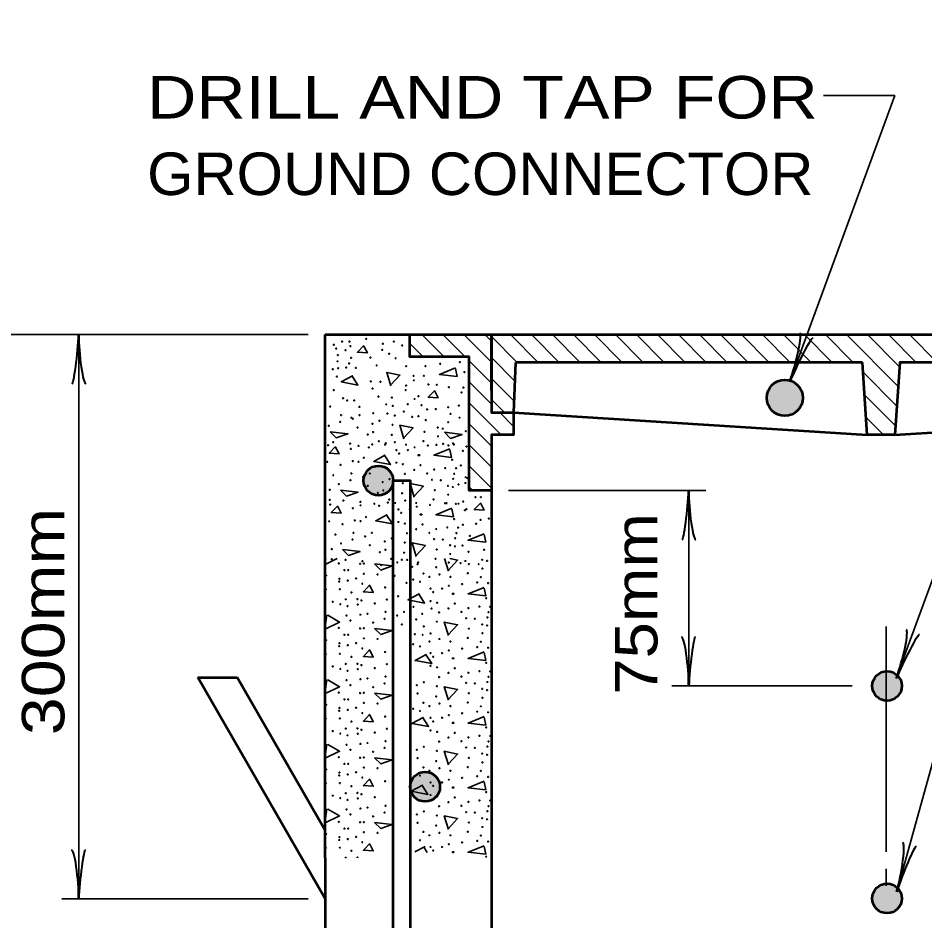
# Model space of a CAD drawing. Extents: x 918 to 1774, y -8 to 536.
# Drawn here: x 1039.5 to 1103.6, y 193.7 to 257.4 of the extents above; entities that cross this region are included whole.
import ezdxf

# ---------------------------------------------------------------- set-up
doc = ezdxf.new("R2010")
doc.units = 0
doc.header["$LTSCALE"] = 1.2
doc.layers.add('1', color=7, linetype='Continuous', lineweight=35)

msp = doc.modelspace()

# ---------------------------------------------------------------- hatches: boundary and pattern name
at = {"layer": '1'}
for points in [[(1094.941, 230.59, 1), (1092.39, 230.59, 1)], [(1066.027, 224.745, 1), (1063.934, 224.745, 1)], [(1101.93, 210.254, 1), (1099.837, 210.254, 1)], [(1069.326, 203.145, 1), (1067.222, 203.145, 1)], [(1101.93, 195.259, 1), (1099.837, 195.259, 1)]]:
    msp.add_hatch(color=256, dxfattribs=at).paths.add_polyline_path(points)

# ---------------------------------------------------------------- linework, layer by layer
for p, q in [((1060.028, 235.047), (1028.227, 235.047)), ((1043.828, 235.047), (1043.828, 195.243)), ((1069.615, 233.475), (1068.043, 235.047)), ((1071.097, 233.475), (1069.525, 235.047)), ((1072.952, 233.102), (1071.007, 235.047)), ((1072.952, 234.584), (1072.489, 235.047)), ((1072.952, 234.914), (1074.784, 233.082)), ((1074.301, 235.047), (1076.266, 233.082)), ((1075.783, 235.047), (1077.748, 233.082)), ((1077.265, 235.047), (1079.23, 233.082)), ((1078.747, 235.047), (1080.712, 233.082)), ((1080.229, 235.047), (1082.194, 233.082)), ((1081.711, 235.047), (1083.676, 233.082)), ((1083.193, 235.047), (1085.158, 233.082)), ((1084.675, 235.047), (1086.639, 233.082)), ((1086.157, 235.047), (1088.122, 233.082)), ((1087.639, 235.047), (1089.604, 233.082)), ((1089.121, 235.047), (1091.086, 233.082)), ((1090.603, 235.047), (1092.568, 233.082)), ((1092.085, 235.047), (1094.049, 233.082)), ((1093.567, 235.047), (1095.532, 233.082)), ((1095.049, 235.047), (1097.014, 233.082)), ((1096.531, 235.047), (1098.495, 233.082)), ((1098.013, 235.047), (1101.662, 231.397)), ((1099.495, 235.047), (1101.758, 232.783)), ((1100.977, 235.047), (1102.942, 233.082)), ((1102.459, 235.047), (1104.424, 233.082)), ((1068.133, 233.475), (1067.188, 234.42)), ((1072.952, 231.621), (1071.38, 233.192)), ((1072.952, 233.432), (1074.609, 231.775)), ((1099.188, 232.389), (1101.567, 230.011)), ((1072.952, 231.95), (1074.554, 230.347)), ((1072.952, 230.138), (1071.38, 231.71)), ((1072.952, 230.468), (1073.874, 229.545)), ((1099.298, 230.797), (1101.471, 228.624)), ((1073.635, 227.973), (1071.38, 230.228)), ((1074.523, 228.567), (1073.545, 229.545)), ((1099.408, 229.205), (1100.64, 227.973)), ((1072.952, 227.175), (1071.38, 228.746)), ((1072.952, 225.692), (1071.38, 227.264)), ((1072.952, 224.211), (1071.38, 225.782)), ((1071.08, 225.019), (1071.38, 224.847)), ((1071.637, 224.043), (1071.38, 224.3)), ((1074.151, 224.043), (1088.09, 224.043)), ((1086.889, 210.254), (1086.889, 224.043)), ((1062.07, 219.243), (1061.227, 218.832)), ((1061.227, 218.98), (1061.265, 219.243)), ((1069.917, 218.365), (1069.653, 219.243)), ((1061.227, 214.42), (1061.349, 215.269)), ((1100.828, 214.443), (1100.828, 198.543)), ((1061.227, 209.86), (1061.349, 210.709)), ((1098.428, 210.254), (1085.689, 210.254)), ((1061.227, 205.3), (1061.349, 206.149)), ((1061.227, 200.74), (1061.349, 201.589)), ((1068.27, 198.934), (1067.547, 198.54)), ((1068.425, 198.496), (1068.156, 198.914)), ((1100.828, 197.343), (1100.828, 196.143)), ((1060.028, 195.243), (1042.628, 195.243))]:
    msp.add_line(p, q, dxfattribs=at)
at = {"layer": '1', "lineweight": 53}
for p, q in [((1061.227, 198.122), (1061.227, 235.047)), ((1072.952, 235.047), (1127.967, 235.047)), ((1072.952, 231.117), (1072.952, 235.047)), ((1074.659, 233.082), (1074.523, 229.545)), ((1099.141, 233.082), (1074.659, 233.082)), ((1074.523, 229.545), (1099.493, 227.973)), ((1101.426, 227.973), (1126.396, 229.545)), ((1072.952, 224.043), (1072.952, 198.122)), ((1061.227, 195.243), (1052.227, 210.843)), ((1052.227, 210.843), (1054.998, 210.843)), ((1061.227, 200.046), (1054.998, 210.843)), ((1061.227, 198.122), (1061.227, 163.476)), ((1072.952, 198.122), (1072.952, 158.043))]:
    msp.add_line(p, q, dxfattribs=at)
at = {"layer": '1'}
for points in [[(1101.54, 210.795), (1118.692, 257.384), (1101.575, 195.743)], [(1094.021, 231.736), (1101.428, 251.913), (1096.398, 251.913)], [(1063.958, 234.285), (1063.502, 233.805), (1064.198, 233.757), (1063.958, 234.237)], [(1065.855, 231.427), (1065.567, 232.387), (1066.503, 232.195), (1065.831, 231.475)], [(1070.412, 232.702), (1069.284, 232.246), (1070.532, 232.102), (1070.412, 232.654)], [(1063.148, 232.141), (1062.356, 231.709), (1063.532, 231.493), (1063.1, 232.165)], [(1068.957, 231.114), (1068.501, 230.634), (1069.197, 230.586), (1068.957, 231.066)], [(1066.782, 227.695), (1066.494, 228.655), (1067.43, 228.463), (1066.758, 227.743)], [(1061.96, 227.155), (1061.504, 226.675), (1062.2, 226.627), (1061.96, 227.107)], [(1070.024, 226.987), (1068.896, 226.531), (1070.144, 226.387), (1070.024, 226.939)], [(1065.44, 226.531), (1064.648, 226.099), (1065.824, 225.883), (1065.392, 226.555)], [(1067.504, 223.579), (1067.216, 224.538), (1068.152, 224.347), (1067.48, 223.627)], [(1062.104, 222.966), (1061.648, 222.486), (1062.344, 222.438), (1062.104, 222.918)], [(1070.168, 222.798), (1069.04, 222.342), (1070.288, 222.198), (1070.168, 222.75)], [(1072.201, 223.186), (1071.745, 222.706), (1072.441, 222.658), (1072.201, 223.138)], [(1065.584, 222.342), (1064.792, 221.91), (1065.968, 221.694), (1065.536, 222.366)], [(1072.436, 220.993), (1071.308, 220.537), (1072.556, 220.393), (1072.436, 220.945)], [(1067.648, 219.39), (1067.36, 220.35), (1068.296, 220.158), (1067.624, 219.438)], [(1070.025, 219.243), (1070.565, 219.133), (1069.893, 218.413)], [(1064.373, 217.381), (1063.917, 216.901), (1064.613, 216.853), (1064.373, 217.333)], [(1072.437, 217.213), (1071.309, 216.757), (1072.557, 216.613), (1072.437, 217.165)], [(1067.853, 216.757), (1067.061, 216.325), (1068.237, 216.109), (1067.805, 216.781)], [(1061.397, 215.245), (1062.237, 214.765), (1061.227, 214.272)], [(1069.917, 213.805), (1069.629, 214.765), (1070.565, 214.573), (1069.893, 213.853)], [(1064.373, 212.821), (1063.917, 212.341), (1064.613, 212.293), (1064.373, 212.773)], [(1072.437, 212.653), (1071.309, 212.197), (1072.557, 212.053), (1072.437, 212.605)], [(1068.358, 212.482), (1067.566, 212.05), (1068.742, 211.834), (1068.31, 212.506)], [(1061.397, 210.685), (1062.237, 210.205), (1061.227, 209.712)], [(1069.917, 209.245), (1069.629, 210.205), (1070.565, 210.013), (1069.893, 209.293)], [(1064.373, 208.261), (1063.917, 207.781), (1064.613, 207.733), (1064.373, 208.213)], [(1068.138, 208.032), (1067.346, 207.6), (1068.522, 207.384), (1068.09, 208.056)], [(1072.437, 208.093), (1071.309, 207.637), (1072.557, 207.493), (1072.437, 208.045)], [(1061.397, 206.125), (1062.237, 205.645), (1061.227, 205.152)], [(1069.917, 204.685), (1069.629, 205.645), (1070.565, 205.453), (1069.893, 204.733)], [(1064.373, 203.701), (1063.917, 203.221), (1064.613, 203.173), (1064.373, 203.653)], [(1068.094, 203.252), (1067.302, 202.82), (1068.478, 202.604), (1068.046, 203.276)], [(1072.437, 203.533), (1071.309, 203.077), (1072.557, 202.933), (1072.437, 203.485)], [(1061.397, 201.565), (1062.237, 201.085), (1061.227, 200.592)], [(1069.917, 200.125), (1069.629, 201.085), (1070.565, 200.893), (1069.893, 200.173)], [(1064.373, 199.141), (1063.917, 198.661), (1064.613, 198.613), (1064.373, 199.093)], [(1072.437, 198.973), (1071.309, 198.517), (1072.557, 198.373), (1072.437, 198.925)]]:
    msp.add_lwpolyline(points, dxfattribs=at)
at = {"layer": '1', "lineweight": 53}
for points in [[(1061.227, 235.047), (1072.952, 235.047), (1072.952, 229.545), (1074.523, 229.545), (1074.523, 227.973), (1072.952, 227.973), (1072.952, 224.043), (1071.38, 224.043), (1071.38, 233.475), (1067.188, 233.475), (1067.188, 235.047)], [(1126.26, 233.082), (1101.778, 233.082), (1101.426, 227.973), (1099.493, 227.973), (1099.141, 233.082)]]:
    msp.add_lwpolyline(points, dxfattribs=at)
at = {"layer": '1'}
for points in [[(1061.574, 228.199), (1062.822, 228.055), (1062.006, 227.767)], [(1069.636, 228.156), (1070.884, 228.012), (1070.068, 227.724)], [(1062.296, 224.083), (1063.544, 223.939), (1062.728, 223.651)], [(1062.44, 219.894), (1063.688, 219.75), (1062.872, 219.462)], [(1064.709, 218.869), (1065.957, 218.725), (1065.141, 218.437)], [(1064.709, 214.309), (1065.957, 214.165), (1065.141, 213.877)], [(1064.709, 209.749), (1065.957, 209.605), (1065.141, 209.317)], [(1064.709, 205.189), (1065.957, 205.045), (1065.141, 204.757)], [(1064.709, 200.629), (1065.957, 200.485), (1065.141, 200.197)]]:
    msp.add_lwpolyline(points, close=True, dxfattribs=at)
at = {"layer": '1', "lineweight": 53}
msp.add_lwpolyline([(1066.028, 152.043), (1066.028, 224.745), (1067.227, 224.745), (1067.227, 153.243), (1091.227, 153.243), (1091.227, 152.043)], close=True, dxfattribs=at)
at = {"layer": '1'}
for centre in [(1061.831, 234.336), (1062.417, 234.555), (1062.929, 234.555), (1064.124, 234.751), (1065.294, 234.409), (1066.075, 234.555), (1066.66, 234.287), (1062.002, 234.068), (1062.124, 233.604), (1062.661, 233.946), (1063.002, 234.238), (1065.246, 233.97), (1065.733, 233.702), (1062.1, 233.165), (1062.904, 233.019), (1063.051, 233.409), (1064.416, 233.433), (1066.197, 233.385), (1069.343, 232.994), (1070.733, 233.116), (1061.758, 232.604), (1062.148, 232.677), (1062.709, 232.726), (1063.392, 232.701), (1064.855, 232.872), (1066.928, 232.823), (1068.294, 232.823), (1071.05, 232.409), (1062.051, 232.092), (1064.441, 231.75), (1065.124, 231.726), (1067.465, 232.14), (1067.489, 231.823), (1068.196, 232.14), (1061.831, 231.14), (1064.563, 231.238), (1066.904, 231.14), (1066.928, 231.457), (1068.513, 231.531), (1069.099, 231.506), (1069.952, 231.335), (1070.976, 231.311), (1062.49, 230.555), (1062.783, 230.408), (1063.27, 230.408), (1064.977, 230.677), (1065.928, 230.604), (1067.538, 230.506), (1067.806, 230.701), (1070.855, 230.969), (1061.583, 229.971), (1063.636, 229.945), (1065.528, 230.13), (1065.989, 230.019), (1067.05, 230.14), (1068.026, 230.067), (1068.416, 229.774), (1069.026, 229.798), (1069.903, 229.92), (1070.659, 230.042), (1062.347, 229.367), (1063.075, 229.189), (1063.651, 229.367), (1064.612, 229.506), (1065.611, 229.481), (1066.132, 229.335), (1066.784, 229.621), (1067.367, 229.237), (1067.806, 229.286), (1070.074, 229.457), (1070.708, 229.189), (1061.472, 228.619), (1062.283, 228.889), (1063.174, 229.112), (1063.508, 228.492), (1064.557, 228.762), (1065.05, 228.969), (1065.973, 228.683), (1068.318, 229.018), (1069.17, 228.492), (1069.903, 228.872), (1064.224, 227.999), (1064.605, 228.174), (1065.925, 227.967), (1068.231, 228.19), (1069.186, 227.871), (1069.519, 228.412), (1071.142, 228.237), (1061.431, 227.239), (1061.79, 227.458), (1062.983, 227.362), (1064.548, 227.303), (1065.019, 227.521), (1065.448, 227.283), (1065.502, 227.382), (1066.148, 227.458), (1066.927, 227.283), (1068.152, 227.537), (1068.476, 227.223), (1069.074, 227.267), (1069.542, 227.335), (1069.917, 227.235), (1070.251, 227.378), (1070.305, 227.287), (1063.037, 226.985), (1063.578, 227.191), (1064.303, 227.092), (1066.249, 226.905), (1066.44, 226.65), (1067.061, 226.905), (1067.538, 227.096), (1070.941, 226.841), (1071.189, 227.155), (1061.367, 226.062), (1063.164, 226.125), (1063.578, 226.078), (1063.959, 226.364), (1066.25, 226.014), (1067.808, 226.539), (1067.872, 226.539), (1070.178, 226.221), (1062.305, 225.855), (1066.711, 225.903), (1067.506, 225.505), (1067.951, 225.839), (1068.921, 225.521), (1069.701, 225.632), (1070.464, 225.616), (1070.798, 225.823), (1061.796, 225.123), (1063.005, 224.773), (1063.069, 225.25), (1063.896, 224.996), (1064.373, 225.25), (1065.279, 224.646), (1065.772, 224.853), (1066.854, 225.219), (1068.428, 225.25), (1068.762, 224.805), (1069.383, 224.773), (1070.257, 224.869), (1070.337, 225.235), (1061.542, 224.105), (1062.194, 224.503), (1064.23, 224.375), (1065.327, 224.057), (1066.695, 224.566), (1068.953, 224.073), (1069.891, 224.375), (1070.241, 224.296), (1070.632, 224.482), (1071.119, 224.579), (1061.542, 223.389), (1064.945, 223.882), (1065.741, 223.405), (1066.647, 223.85), (1068.874, 223.421), (1069.907, 223.755), (1071.827, 223.579), (1072.217, 223.579), (1061.575, 223.051), (1062.512, 223.341), (1063.181, 222.796), (1063.705, 223.246), (1063.722, 223.003), (1064.692, 223.114), (1065.025, 222.976), (1065.646, 223.194), (1066.17, 223.166), (1066.87, 223.341), (1067.649, 223.166), (1067.682, 222.907), (1068.62, 223.035), (1069.686, 223.146), (1069.796, 223.151), (1070.449, 223.098), (1070.639, 223.119), (1070.973, 223.262), (1071.192, 222.725), (1064.104, 222.176), (1066.394, 222.717), (1066.585, 222.462), (1067.205, 222.717), (1067.953, 222.351), (1068.016, 222.351), (1071.086, 222.653), (1061.512, 221.873), (1062.45, 221.666), (1063.309, 221.937), (1063.722, 221.889), (1066.394, 221.826), (1066.855, 221.714), (1068.096, 221.651), (1069.845, 221.444), (1070.322, 222.032), (1070.942, 221.635), (1071.875, 221.701), (1072.192, 221.969), (1072.778, 222.066), (1061.941, 220.935), (1063.213, 221.062), (1064.04, 220.807), (1064.517, 221.062), (1066.998, 221.03), (1067.65, 221.317), (1068.573, 221.062), (1069.066, 221.332), (1070.481, 221.046), (1070.608, 221.428), (1071.436, 220.847), (1062.338, 220.314), (1063.15, 220.585), (1064.374, 220.187), (1065.424, 220.457), (1065.917, 220.664), (1066.839, 220.378), (1068.907, 220.617), (1069.527, 220.585), (1070.036, 220.187), (1070.402, 220.68), (1070.924, 220.164), (1061.686, 219.917), (1065.09, 219.694), (1065.472, 219.869), (1066.792, 219.662), (1069.098, 219.885), (1070.052, 219.567), (1070.386, 220.107), (1071.339, 219.725), (1072.436, 219.871), (1061.686, 219.201), (1062.18, 218.907), (1062.657, 219.153), (1063.849, 219.057), (1063.955, 218.891), (1065.885, 219.217), (1066.314, 218.978), (1066.643, 219.162), (1067.014, 219.153), (1067.793, 218.978), (1069.018, 219.232), (1069.941, 218.962), (1070.783, 218.93), (1071.117, 219.073), (1072.304, 219.162), (1072.654, 219.082), (1062.578, 218.43), (1062.848, 218.43), (1063.683, 218.873), (1065.169, 218.787), (1067.358, 218.669), (1067.74, 218.844), (1069.06, 218.637), (1071.366, 218.859), (1072.056, 218.851), (1072.32, 218.541), (1061.29, 218.048), (1062.212, 217.624), (1062.228, 217.825), (1062.816, 217.688), (1063.405, 217.841), (1063.955, 218.175), (1064.925, 218.128), (1066.118, 218.032), (1067.438, 217.762), (1067.915, 217.608), (1068.153, 218.191), (1068.583, 217.953), (1069.283, 218.128), (1070.062, 217.953), (1071.286, 218.207), (1072.209, 217.937), (1062.26, 217.083), (1063.844, 217.465), (1065.45, 217.211), (1065.991, 217.417), (1066.961, 217.529), (1068.662, 217.131), (1069.473, 217.131), (1069.951, 217.322), (1070.889, 217.449), (1071.954, 217.561), (1072.718, 217.513), (1062.673, 216.368), (1063.071, 216.861), (1063.5, 216.383), (1065.577, 216.352), (1066.372, 216.59), (1068.853, 216.877), (1070.221, 216.765), (1070.285, 216.765), (1072.591, 216.447), (1061.751, 216.193), (1062.292, 216.018), (1062.801, 215.89), (1063.516, 216.002), (1063.78, 216.288), (1064.718, 216.081), (1065.991, 216.304), (1067.457, 215.837), (1068.662, 216.24), (1068.735, 215.711), (1069.124, 216.129), (1069.919, 215.731), (1070.364, 216.065), (1071.334, 215.747), (1072.113, 215.859), (1072.877, 215.843), (1062.737, 215.222), (1063.707, 215.286), (1064.209, 215.349), (1065.482, 215.477), (1066.309, 215.222), (1066.786, 215.477), (1068.077, 215.344), (1069.267, 215.445), (1070.841, 215.477), (1072.67, 215.095), (1072.75, 215.461), (1063.007, 214.872), (1064.607, 214.729), (1065.418, 214.999), (1066.643, 214.602), (1067.647, 214.951), (1068.179, 214.458), (1069.108, 214.793), (1071.175, 215.031), (1071.795, 214.999), (1072.304, 214.602), (1072.654, 214.522), (1062.18, 214.347), (1062.578, 213.87), (1062.848, 213.87), (1063.683, 214.313), (1063.955, 214.331), (1067.559, 213.901), (1068.103, 213.863), (1068.659, 213.964), (1071.366, 214.299), (1072.32, 213.981), (1061.29, 213.488), (1062.228, 213.265), (1062.816, 213.128), (1063.405, 213.281), (1063.955, 213.615), (1064.925, 213.568), (1067.438, 213.202), (1068.583, 213.393), (1069.283, 213.568), (1070.062, 213.393), (1071.286, 213.647), (1072.209, 213.377), (1062.212, 213.064), (1062.26, 212.523), (1063.844, 212.905), (1065.45, 212.651), (1067.915, 213.048), (1068.662, 212.571), (1069.473, 212.571), (1069.951, 212.762), (1070.889, 212.889), (1071.954, 213.001), (1072.718, 212.953), (1063.071, 212.301), (1068.853, 212.317), (1070.221, 212.205), (1070.285, 212.205), (1072.591, 211.887), (1061.751, 211.633), (1062.292, 211.458), (1062.673, 211.808), (1062.801, 211.33), (1063.5, 211.823), (1063.516, 211.442), (1063.78, 211.728), (1064.718, 211.521), (1065.577, 211.792), (1068.662, 211.68), (1069.124, 211.569), (1070.364, 211.505), (1072.113, 211.299), (1072.877, 211.283), (1062.737, 210.662), (1063.707, 210.726), (1064.209, 210.789), (1065.482, 210.917), (1069.267, 210.885), (1069.919, 211.171), (1070.841, 210.917), (1071.334, 211.187), (1072.75, 210.901), (1063.007, 210.312), (1064.607, 210.169), (1065.418, 210.439), (1067.692, 210.312), (1068.185, 210.519), (1069.108, 210.233), (1071.175, 210.471), (1071.795, 210.439), (1072.304, 210.042), (1072.654, 209.962), (1072.67, 210.535), (1062.18, 209.787), (1062.578, 209.31), (1062.848, 209.31), (1063.683, 209.753), (1063.955, 209.771), (1067.74, 209.724), (1069.06, 209.517), (1071.366, 209.739), (1072.32, 209.421), (1061.29, 208.928), (1062.228, 208.705), (1063.405, 208.721), (1063.955, 209.055), (1064.925, 209.008), (1067.438, 208.642), (1068.153, 209.071), (1068.583, 208.833), (1069.283, 209.008), (1070.062, 208.833), (1071.286, 209.087), (1072.209, 208.817), (1062.212, 208.504), (1062.816, 208.568), (1063.844, 208.345), (1065.45, 208.091), (1067.915, 208.488), (1068.662, 208.011), (1069.473, 208.011), (1069.951, 208.202), (1070.889, 208.329), (1071.954, 208.441), (1072.718, 208.393), (1062.26, 207.963), (1063.071, 207.741), (1068.853, 207.757), (1070.221, 207.645), (1070.285, 207.645), (1061.751, 207.073), (1062.292, 206.898), (1062.673, 207.248), (1062.801, 206.77), (1063.5, 207.263), (1063.516, 206.882), (1063.78, 207.168), (1064.718, 206.961), (1065.577, 207.232), (1068.662, 207.12), (1069.124, 207.009), (1070.364, 206.945), (1072.113, 206.739), (1072.591, 207.327), (1072.877, 206.723), (1062.737, 206.102), (1063.707, 206.166), (1064.209, 206.229), (1065.482, 206.357), (1069.267, 206.325), (1069.919, 206.611), (1070.841, 206.357), (1071.334, 206.627), (1072.75, 206.341), (1063.007, 205.752), (1064.607, 205.609), (1065.418, 205.879), (1067.692, 205.752), (1068.185, 205.959), (1069.108, 205.673), (1071.175, 205.911), (1071.795, 205.879), (1072.304, 205.482), (1072.67, 205.975), (1062.18, 205.227), (1063.683, 205.193), (1063.955, 205.211), (1067.74, 205.164), (1069.06, 204.957), (1071.366, 205.179), (1072.32, 204.861), (1072.654, 205.402), (1061.29, 204.368), (1062.578, 204.75), (1062.848, 204.75), (1063.405, 204.161), (1063.955, 204.495), (1064.925, 204.448), (1068.153, 204.511), (1068.583, 204.273), (1069.283, 204.448), (1070.062, 204.273), (1071.286, 204.527), (1072.209, 204.257), (1062.212, 203.944), (1062.228, 204.145), (1062.816, 204.008), (1063.844, 203.785), (1065.45, 203.531), (1067.915, 203.928), (1069.951, 203.642), (1070.889, 203.769), (1071.954, 203.881), (1072.718, 203.833), (1062.26, 203.403), (1063.071, 203.181), (1068.662, 203.451), (1068.853, 203.197), (1069.473, 203.451), (1070.221, 203.085), (1070.285, 203.085), (1061.751, 202.513), (1062.292, 202.338), (1062.673, 202.688), (1063.5, 202.703), (1063.516, 202.322), (1063.78, 202.608), (1064.718, 202.401), (1068.662, 202.56), (1069.124, 202.449), (1070.364, 202.385), (1072.591, 202.767), (1062.801, 202.21), (1063.707, 201.606), (1064.209, 201.669), (1065.482, 201.797), (1069.267, 201.765), (1069.919, 202.051), (1070.841, 201.797), (1071.334, 202.067), (1072.113, 202.179), (1072.75, 201.781), (1072.877, 202.163), (1062.737, 201.542), (1063.007, 201.192), (1064.607, 201.049), (1065.418, 201.319), (1067.692, 201.192), (1068.185, 201.399), (1069.108, 201.113), (1071.175, 201.351), (1071.795, 201.319), (1072.67, 201.415), (1062.18, 200.667), (1063.683, 200.633), (1063.955, 200.651), (1067.74, 200.604), (1069.06, 200.397), (1071.366, 200.619), (1072.304, 200.922), (1072.654, 200.842), (1061.29, 199.808), (1062.578, 200.19), (1062.848, 200.19), (1063.955, 199.935), (1064.925, 199.888), (1068.153, 199.951), (1068.583, 199.713), (1069.283, 199.888), (1070.062, 199.713), (1071.286, 199.967), (1072.209, 199.697), (1072.32, 200.301), (1062.212, 199.384), (1062.228, 199.585), (1062.816, 199.448), (1063.405, 199.601), (1063.844, 199.225), (1067.915, 199.368), (1069.951, 199.082), (1070.889, 199.209), (1071.954, 199.321), (1072.718, 199.273), (1062.26, 198.843), (1063.071, 198.621), (1068.662, 198.891), (1068.853, 198.637), (1069.473, 198.891), (1070.221, 198.525), (1070.285, 198.525), (1072.591, 198.207)]:
    msp.add_circle(centre, 0.0318, dxfattribs=at)
at = {"layer": '1', "lineweight": 53}
for centre, radius in [((1093.665, 230.59), 1.276), ((1064.981, 224.745), 1.047), ((1100.884, 210.254), 1.047), ((1068.274, 203.145), 1.052), ((1100.884, 195.259), 1.047)]:
    msp.add_circle(centre, radius, dxfattribs=at)
at = {"layer": '1'}
for centre, start, end in [((1061.258, 217.068), 196.73563, 163.26437), ((1061.258, 212.508), 196.73563, 163.26437), ((1061.258, 207.948), 196.73563, 163.26437), ((1061.258, 203.388), 196.73563, 163.26437), ((1061.258, 198.828), 196.73563, 163.26437), ((1062.673, 198.128), 350.65784, 189.34216), ((1063.5, 198.143), 318.40069, 221.59931)]:
    msp.add_arc(centre, 0.0318, start, end, dxfattribs=at)
at = {"layer": '1', "lineweight": 40}
for centre, major_axis, ratio, start_param, end_param in [((1043.564, 233.691), (0.211, 2.108), 0.07063, 3.140715, 5.41811), ((1044.149, 233.726), (-0.187, 2.143), 0.122415, 0.896353, 3.141593), ((1094.161, 233.08), (-0.562, -2.076), 0.122415, 0.896353, 3.141593), ((1094.723, 232.911), (0.924, 1.906), 0.07063, 6.282307, 8.559703), ((1086.626, 222.688), (0.211, 2.108), 0.07063, 3.140715, 5.41811), ((1087.211, 222.723), (-0.187, 2.143), 0.122415, 0.896353, 3.141593), ((1101.681, 212.138), (-0.564, -2.076), 0.122415, 0.896353, 3.141593), ((1102.243, 211.969), (-0.926, -1.905), 0.07063, 3.140715, 5.41811), ((1086.558, 211.564), (0.187, -2.143), 0.122415, 0.896353, 3.141593), ((1087.143, 211.599), (-0.211, -2.108), 0.07063, 3.140715, 5.41811), ((1101.606, 197.093), (-0.393, -2.115), 0.122415, 0.896353, 3.141593), ((1043.496, 196.553), (0.187, -2.143), 0.122415, 0.896353, 3.141593), ((1044.081, 196.588), (-0.211, -2.108), 0.07063, 3.140715, 5.41811), ((1102.179, 196.971), (-0.767, -1.974), 0.07063, 3.140715, 5.41811)]:
    msp.add_ellipse(centre, major_axis=major_axis, ratio=ratio, start_param=start_param, end_param=end_param, dxfattribs=at)

# ---------------------------------------------------------------- texts
at = {"layer": '1'}
for s, width, p in [('DRILL AND TAP FOR', 1.2, (1048.65, 250.3)), ('GROUND CONNECTOR', 1.05, (1048.65, 244.9))]:
    msp.add_text(s, height=3, dxfattribs=dict(at, width=width)).set_placement(p)
for s, width, p in [('300mm', 1.2, (1042.809, 206.78)), ('75mm', 1.15, (1084.675, 209.631))]:
    msp.add_text(s, height=3, rotation=90, dxfattribs=dict(at, width=width)).set_placement(p)

doc.saveas('drawing.dxf')
